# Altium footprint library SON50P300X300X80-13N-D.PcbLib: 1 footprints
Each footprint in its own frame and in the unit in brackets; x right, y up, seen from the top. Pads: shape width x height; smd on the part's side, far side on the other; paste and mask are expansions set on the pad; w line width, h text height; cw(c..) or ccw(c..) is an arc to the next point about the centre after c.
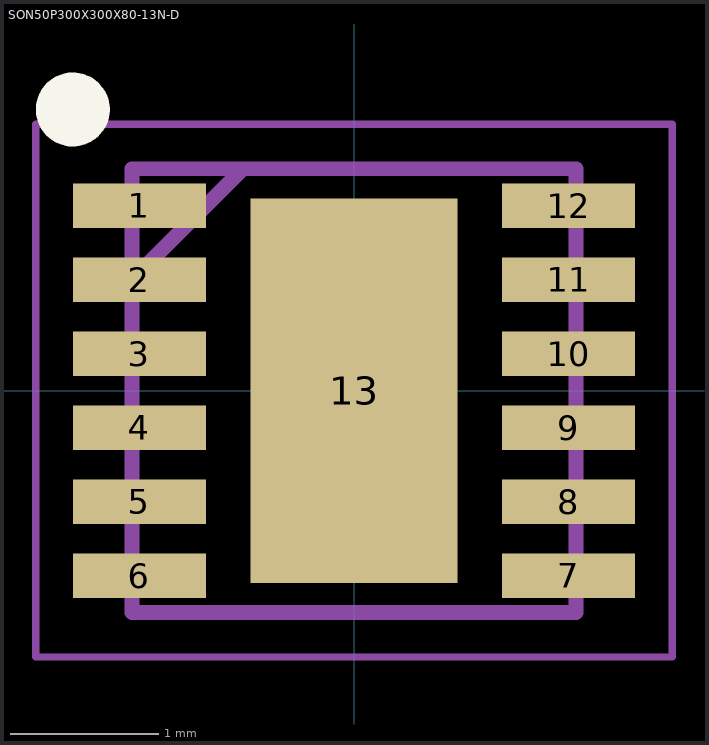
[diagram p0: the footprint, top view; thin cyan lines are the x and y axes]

## SON50P300X300X80-13N-D [mm]
pads (13):
  rect 0.9x0.3 smd: 1(-1.45,1.25) 2(-1.45,0.75) 3(-1.45,0.25) 4(-1.45,-0.25) 5(-1.45,-0.75) 6(-1.45,-1.25) 7(1.45,-1.25) 8(1.45,-0.75) 9(1.45,-0.25) 10(1.45,0.25) 11(1.45,0.75) 12(1.45,1.25)
  rect 1.4x2.6 smd: 13(0,0)
Top Overlay:
  circle w0.25: c-1.9,1.9 r0.125
Mechanical 15:
  lines w0.1: -1.5,0.75 -0.75,1.5 ; -1.5,-1.5 1.5,-1.5 1.5,1.5 -1.5,1.5 -1.5,-1.5
Mechanical 20:
  lines w0.05: -2.15,-1.8 2.15,-1.8 2.15,1.8 -2.15,1.8 -2.15,-1.8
